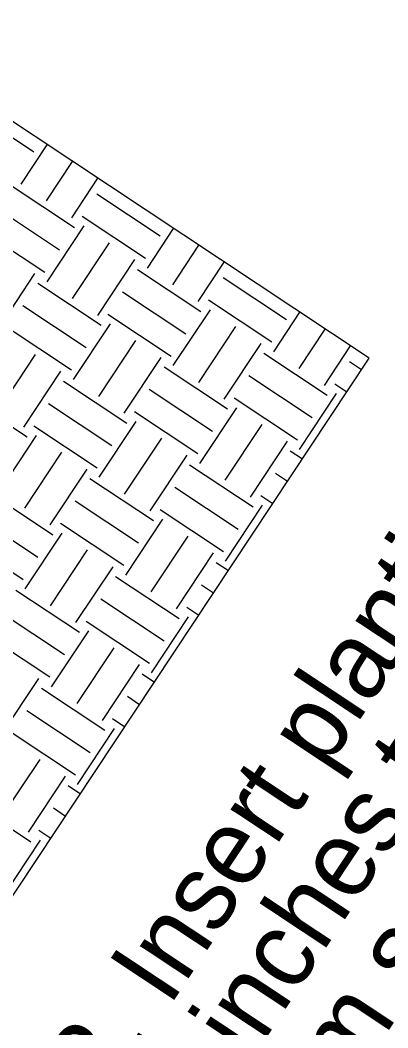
# Model space of a CAD drawing. Extents: x 561231 to 564935, y 589159 to 602519.
# Drawn here: x 564310.3 to 564329.7, y 589788.4 to 589841.6 of the extents above; entities that cross this region are included whole.
import ezdxf

# ---------------------------------------------------------------- set-up
doc = ezdxf.new("R2010")
doc.units = 0
doc.layers.add('Old_Level_1', color=7, linetype='Continuous')

msp = doc.modelspace()

# ---------------------------------------------------------------- linework, layer by layer
at = {"layer": 'Old_Level_1'}
for p, q in [((564328.717, 589823.733), (564301.831, 589841.57)), ((564307.685, 589836.836), (564311.031, 589834.617)), ((564310.351, 589832.916), (564311.734, 589835)), ((564311.689, 589832.028), (564313.071, 589834.113)), ((564313.027, 589831.14), (564314.409, 589833.225)), ((564309.821, 589832.843), (564313.166, 589830.624)), ((564314.353, 589832.413), (564317.698, 589830.193)), ((564309.04, 589831.664), (564312.385, 589829.445)), ((564313.571, 589831.234), (564316.917, 589829.015)), ((564308.258, 589830.487), (564311.603, 589828.267)), ((564311.719, 589827.766), (564313.673, 589830.711)), ((564317.018, 589828.492), (564318.401, 589830.577)), ((564313.057, 589826.878), (564315.011, 589829.824)), ((564318.356, 589827.605), (564319.739, 589829.689)), ((564314.396, 589825.991), (564316.349, 589828.936)), ((564319.694, 589826.717), (564321.077, 589828.802)), ((564316.488, 589828.42), (564319.833, 589826.2)), ((564309.12, 589825.249), (564311.074, 589828.194)), ((564321.02, 589827.989), (564324.365, 589825.77)), ((564311.227, 589827.7), (564314.572, 589825.48)), ((564315.707, 589827.241), (564319.052, 589825.022)), ((564320.238, 589826.811), (564323.584, 589824.591)), ((564310.446, 589826.521), (564313.791, 589824.302)), ((564318.386, 589823.343), (564320.34, 589826.288)), ((564323.685, 589824.069), (564325.068, 589826.154)), ((564314.925, 589826.063), (564318.27, 589823.844)), ((564309.664, 589825.343), (564313.009, 589823.124)), ((564313.111, 589822.601), (564315.064, 589825.547)), ((564319.724, 589822.455), (564321.678, 589825.401)), ((564325.023, 589823.181), (564326.406, 589825.266)), ((564314.449, 589821.713), (564316.402, 589824.659)), ((564321.063, 589821.567), (564323.016, 589824.513)), ((564323.155, 589823.996), (564326.5, 589821.777)), ((564326.361, 589822.293), (564327.744, 589824.379)), ((564305.495, 589788.716), (564328.717, 589823.733)), ((564309.151, 589820.987), (564311.104, 589823.933)), ((564315.787, 589820.826), (564317.741, 589823.771)), ((564327.687, 589823.566), (564328.326, 589823.142)), ((564310.489, 589820.099), (564312.442, 589823.045)), ((564317.894, 589823.276), (564321.239, 589821.057)), ((564312.581, 589822.528), (564315.926, 589820.309)), ((564322.374, 589822.818), (564325.719, 589820.599)), ((564317.113, 589822.098), (564320.458, 589819.878)), ((564325.053, 589818.919), (564327.007, 589821.865)), ((564326.905, 589822.387), (564327.544, 589821.964)), ((564307.32, 589821.808), (564310.665, 589819.589)), ((564311.8, 589821.35), (564315.145, 589819.131)), ((564321.592, 589821.64), (564324.938, 589819.42)), ((564316.331, 589820.92), (564319.676, 589818.7)), ((564319.778, 589818.178), (564321.731, 589821.123)), ((564314.479, 589817.452), (564316.433, 589820.397)), ((564311.018, 589820.172), (564314.364, 589817.952)), ((564321.116, 589817.29), (564323.07, 589820.236)), ((564309.204, 589816.71), (564311.157, 589819.656)), ((564315.817, 589816.564), (564317.771, 589819.509)), ((564322.454, 589816.402), (564324.408, 589819.348)), ((564310.542, 589815.822), (564312.496, 589818.768)), ((564324.561, 589818.853), (564325.2, 589818.429)), ((564317.156, 589815.676), (564319.109, 589818.622)), ((564311.88, 589814.935), (564313.834, 589817.88)), ((564319.248, 589818.105), (564322.593, 589815.886)), ((564323.78, 589817.674), (564324.418, 589817.251)), ((564313.987, 589817.385), (564317.332, 589815.165)), ((564308.674, 589816.637), (564312.019, 589814.418)), ((564318.467, 589816.927), (564321.812, 589814.707)), ((564313.206, 589816.207), (564316.551, 589813.987)), ((564322.998, 589816.496), (564323.637, 589816.073)), ((564317.685, 589815.749), (564321.031, 589813.529)), ((564321.146, 589813.028), (564323.1, 589815.974)), ((564307.893, 589815.459), (564311.238, 589813.239)), ((564312.424, 589815.028), (564315.769, 589812.809)), ((564315.871, 589812.286), (564317.825, 589815.233)), ((564310.572, 589811.561), (564312.526, 589814.506)), ((564307.111, 589814.281), (564310.457, 589812.061)), ((564317.209, 589811.399), (564319.163, 589814.345)), ((564311.91, 589810.673), (564313.864, 589813.618)), ((564318.547, 589810.511), (564320.501, 589813.457)), ((564320.654, 589812.961), (564321.293, 589812.538)), ((564313.248, 589809.785), (564315.202, 589812.73)), ((564315.341, 589812.214), (564318.686, 589809.994)), ((564319.873, 589811.783), (564320.511, 589811.36)), ((564310.08, 589811.494), (564313.425, 589809.274)), ((564314.56, 589811.036), (564317.905, 589808.816)), ((564309.299, 589810.315), (564312.644, 589808.096)), ((564319.091, 589810.605), (564319.73, 589810.181)), ((564313.778, 589809.857), (564317.123, 589807.638)), ((564317.239, 589807.137), (564319.193, 589810.083)), ((564308.517, 589809.137), (564311.863, 589806.918)), ((564311.964, 589806.395), (564313.918, 589809.341)), ((564313.302, 589805.508), (564315.256, 589808.453)), ((564314.64, 589804.62), (564316.594, 589807.565)), ((564316.747, 589807.07), (564317.386, 589806.647)), ((564309.341, 589803.894), (564311.295, 589806.84)), ((564311.434, 589806.323), (564314.779, 589804.103)), ((564315.966, 589805.892), (564316.605, 589805.468)), ((564310.653, 589805.144), (564313.998, 589802.925)), ((564315.184, 589804.714), (564315.823, 589804.29)), ((564309.871, 589803.966), (564313.216, 589801.747)), ((564313.333, 589801.246), (564315.286, 589804.191)), ((564309.395, 589799.617), (564311.349, 589802.562)), ((564310.733, 589798.729), (564312.687, 589801.674)), ((564312.84, 589801.179), (564313.479, 589800.755)), ((564307.527, 589800.431), (564310.873, 589798.212)), ((564312.059, 589800.001), (564312.698, 589799.577)), ((564311.278, 589798.823), (564311.916, 589798.399)), ((564309.425, 589795.355), (564311.379, 589798.3))]:
    msp.add_line(p, q, dxfattribs=at)

# ---------------------------------------------------------------- texts
for s, p in [(' 2 inches toward planter ', (564319.165, 589781.633)), ('3. Insert planting bar ', (564314.863, 589784.486)), (' from seedling.', (564323.466, 589778.781))]:
    msp.add_text(s, height=4.01452, rotation=56.4482, dxfattribs=at).set_placement(p)

doc.saveas('drawing.dxf')
